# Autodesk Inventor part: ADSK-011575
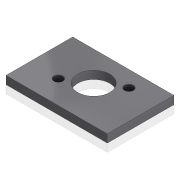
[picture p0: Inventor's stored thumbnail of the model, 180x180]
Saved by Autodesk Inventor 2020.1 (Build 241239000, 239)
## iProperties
Created: 2000-02
Part Number: ADSK-011575
Document SubType Name: Modeling
Designer: sspink
Material: Acier doux
Density: 7.86 g/cm^3
Appearance: Metal-Steel(Polish)
Mass: 154.6 g
Surface Area: 87.7139 cm^2
Volume: 19.6693 cm^3
Control State: 0
Master: False
Checked Out: False
Shininess: 60.0
Length Units: 11269
Angle Units: 11279
Time Units: 11290
Mass Units: 11283
Length Display Precision: 3
Angle Display Precision: 2
Compacted: True
Cutlength: 3
Material Description: FLAT,HRS,0.250X02.000
Material_Number: A084333
Dimensions: 6x50x76 mm
Mass: 0,155 kg
VLT_Material: Acier doux
Density: 7.859999999999999
Volumn: 196.64476800000017
Area: 470.96680000000003
PropertySet Name: Model Information
Author: sspink
Revision Number: -
Title: ADSK-011575
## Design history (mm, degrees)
node "Extrusion1" dims "d2" = 50, "d3" = 0
  sketch "Sketch1"
    geometry: L1 (0, 0)-(76, 0); L2 (76, 0)-(76, 6); L3 (76, 6)-(0, 6); L4 (0, 6)-(0, 0)
    constraints: 8 end point, 2 parallel, 1 horizontal, 1 perpendicular
    dimensions: "d0" = 76 distance of L1.start L1.end; "d1" = 6 distance between parallel lines of L1 L3
node "Hole1" dims "d9" = 6.647, "d10" = 9.525, "d11" = 6.35, "d12" = 60 deg, "d13" = 22.2, "d14" = 118 deg, "d25" = 16
  sketch "Sketch2"
    geometry: L1 (76, 0)-(0, 0) reference; L2 (21.75, -32.5)-(54.25, -32.5); L3 (54.25, -32.5)-(54.25, -12); L4 (54.25, -12)-(21.75, -12); L5 (21.75, -12)-(21.75, -32.5); 4 further points
    constraints: 8 end point, 2 coincident, 2 midpoint, 2 parallel, 1 horizontal, 1 perpendicular, 1 vertical alignment
    dimensions: "d22" = 32.5 distance of L3.end L4.end; "d23" = 20.5 distance of L4.end L2.start; "d24" = 12 distance between parallel lines of L1 L4
node "Hole2" dims "d16" = 24, "d17" = 9.525, "d18" = 6.35, "d19" = 60 deg, "d20" = 19.05, "d21" = 118 deg, "d26" = 6
node "Solide1"
node "Corps solides"
node "Corps surfaciques"
sketch "Sketch3"
  geometry: L1 (0, -50)-(76, -50) reference; L2 (76, 0)-(0, 0) reference; L3 (38, 0)-(38, -50); 1 further point
  constraints: 2 end point, 2 midpoint, 1 point on line
  dimensions: "d15" = 22.225 distance from line of point (38, -22.225) L2
